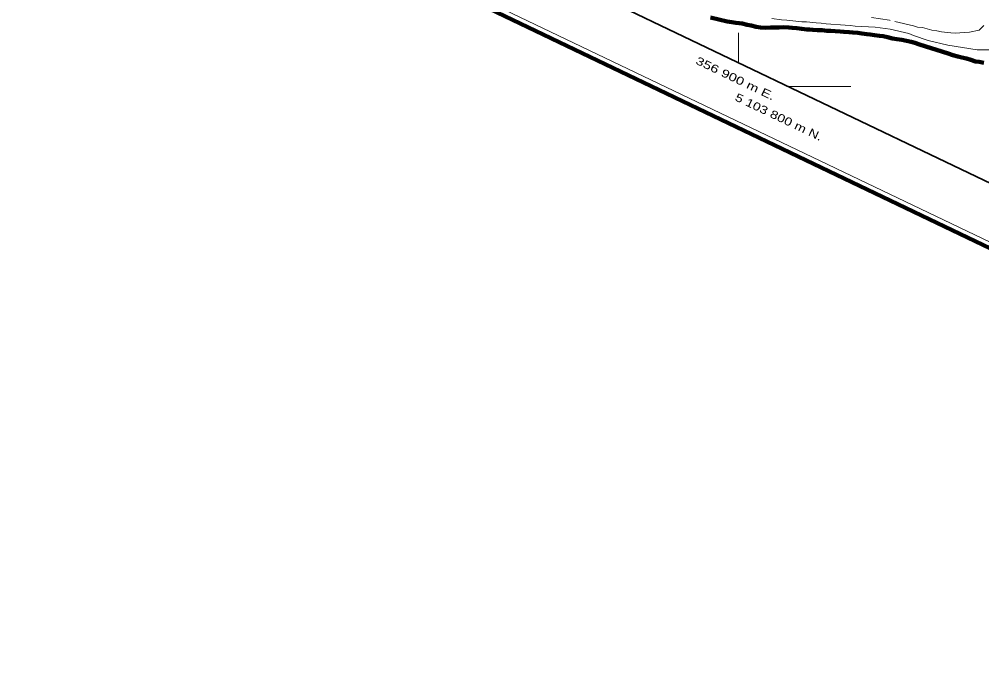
# Model space of a CAD drawing. Extents: x 356765 to 358572, y 5103174 to 5104650.
# Drawn here: x 356765.2 to 356945.5, y 5103689.6 to 5103812.6 of the extents above; entities that cross this region are included whole.
import ezdxf
from ezdxf.enums import TextEntityAlignment as Align

# ---------------------------------------------------------------- set-up
doc = ezdxf.new("R2010")
doc.units = 0
doc.header["$LTSCALE"] = 0.6
doc.linetypes.add('LONG_DASHED', pattern=[7.5, 6, -1.5])
for name, color, linetype, lineweight in [('2', 7, 'Continuous', 13), ('4', 7, 'Continuous', 90), ('60', 7, 'Continuous', 13), ('61', 7, 'Continuous', 13)]:
    doc.layers.add(name, color=color, linetype=linetype, lineweight=lineweight)

msp = doc.modelspace()

# ---------------------------------------------------------------- linework, layer by layer
at = {"layer": '2'}
for points in [[(356947.35, 5103806.88), (356945.49, 5103806.93), (356944.68, 5103806.89), (356939.2, 5103807.77), (356935.52, 5103808.64), (356932.77, 5103809.59), (356931.89, 5103809.98), (356928.36, 5103810.76), (356925.58, 5103811.13), (356921.82, 5103811.35), (356920.9, 5103811.47), (356919.93, 5103811.51), (356916.41, 5103811.8), (356915.49, 5103811.92), (356914.52, 5103811.97), (356912.74, 5103812.17), (356911.85, 5103812.17), (356909.03, 5103812.46), (356908.06, 5103812.51), (356906.21, 5103812.75)], [(356945.96, 5103811.49), (356945.06, 5103810.6)]]:
    msp.add_lwpolyline(points, dxfattribs=at)
at = {"layer": '2', "linetype": 'LONG_DASHED'}
msp.add_lwpolyline([(356945.06, 5103810.6), (356943.23, 5103810.22), (356940.54, 5103810.03), (356939.77, 5103810.07), (356938, 5103810.27), (356937.11, 5103810.47), (356936.19, 5103810.59), (356934.46, 5103811.06), (356933.54, 5103811.18), (356932.77, 5103811.41), (356928.28, 5103812.44), (356924.89, 5103812.94)], dxfattribs=at)
at = {"layer": '4'}
for points in [[(356894.72, 5103812.96), (356897.87, 5103812.19), (356898.72, 5103812.11), (356899.45, 5103811.99), (356900.11, 5103811.92), (356900.65, 5103811.82), (356901.61, 5103811.58), (356902.34, 5103811.47), (356903.3, 5103811.23), (356904.11, 5103811.08), (356905.08, 5103811.03), (356906.01, 5103811.1), (356906.9, 5103811.1), (356907.6, 5103811.1), (356908.42, 5103811.14), (356909.39, 5103811.09), (356910.05, 5103811.02), (356910.9, 5103810.95), (356911.82, 5103810.82), (356912.75, 5103810.7), (356913.25, 5103810.72), (356913.91, 5103810.65), (356914.76, 5103810.57), (356915.65, 5103810.56), (356916.51, 5103810.48), (356917.28, 5103810.45), (356918.06, 5103810.41), (356919.02, 5103810.36), (356919.76, 5103810.25), (356920.72, 5103810.21), (356921.38, 5103810.14), (356922.35, 5103810.09), (356923.08, 5103809.98), (356924.01, 5103809.86), (356924.67, 5103809.79), (356925.48, 5103809.63), (356926.4, 5103809.51), (356927.06, 5103809.44), (356927.87, 5103809.28), (356928.83, 5103809.04), (356929.64, 5103808.89), (356930.56, 5103808.77), (356931.45, 5103808.57), (356932.33, 5103808.37), (356933.02, 5103808.19), (356933.86, 5103807.91), (356939.26, 5103806.19), (356940.1, 5103805.91), (356941.06, 5103805.68), (356941.83, 5103805.45)], [(356941.83, 5103805.45), (356942.71, 5103805.25), (356943.48, 5103805.02), (356944.4, 5103804.7), (356945.06, 5103804.63), (356945.94, 5103804.44)]]:
    msp.add_lwpolyline(points, dxfattribs=at)
at = {"layer": '60', "lineweight": 158}
msp.add_lwpolyline([(356765.24, 5103856.84), (358192.2, 5103173.84), (358571.69, 5103966.7), (357144.73, 5104649.7)], close=True, dxfattribs=at)
at = {"layer": '60'}
msp.add_lwpolyline([(356766.57, 5103857.31), (358191.72, 5103175.17), (358570.35, 5103966.23), (357145.2, 5104648.37)], close=True, dxfattribs=at)
at = {"layer": '60', "lineweight": 35}
msp.add_lwpolyline([(356779.89, 5103862.01), (357952.48, 5103300.77), (358322.47, 5104073.79), (357149.88, 5104635.03)], close=True, dxfattribs=at)
at = {"layer": '61'}
for p, q in [((356900, 5103804.52), (356900, 5103810.06)), ((356909.45, 5103800), (356921.03, 5103800))]:
    msp.add_line(p, q, dxfattribs=at)

# ---------------------------------------------------------------- texts
for s, width, p in [(' 356 900 m E.', 1.35, (356898.7262, 5103801.0314)), (' 5 103 800 m N.', 1.3, (356906.8812, 5103793.8004))]:
    msp.add_text(s, height=1.5, rotation=334.42, dxfattribs=dict(at, width=width)).set_placement(p, align=Align.CENTER)

doc.saveas('drawing.dxf')
